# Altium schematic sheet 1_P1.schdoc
size 355 x 309 mm; Symbol: Sheet-Symbol_A3; Device: Sheet-Symbol_A3; @Page Name: P1; @Create Date: 2022-11-13; @Page Count: 1; @Page No: 1; @Project Name: RGB_语音小灯_RGB; @Schematic Name: Schematic1; @Update Date: 2023-01-12
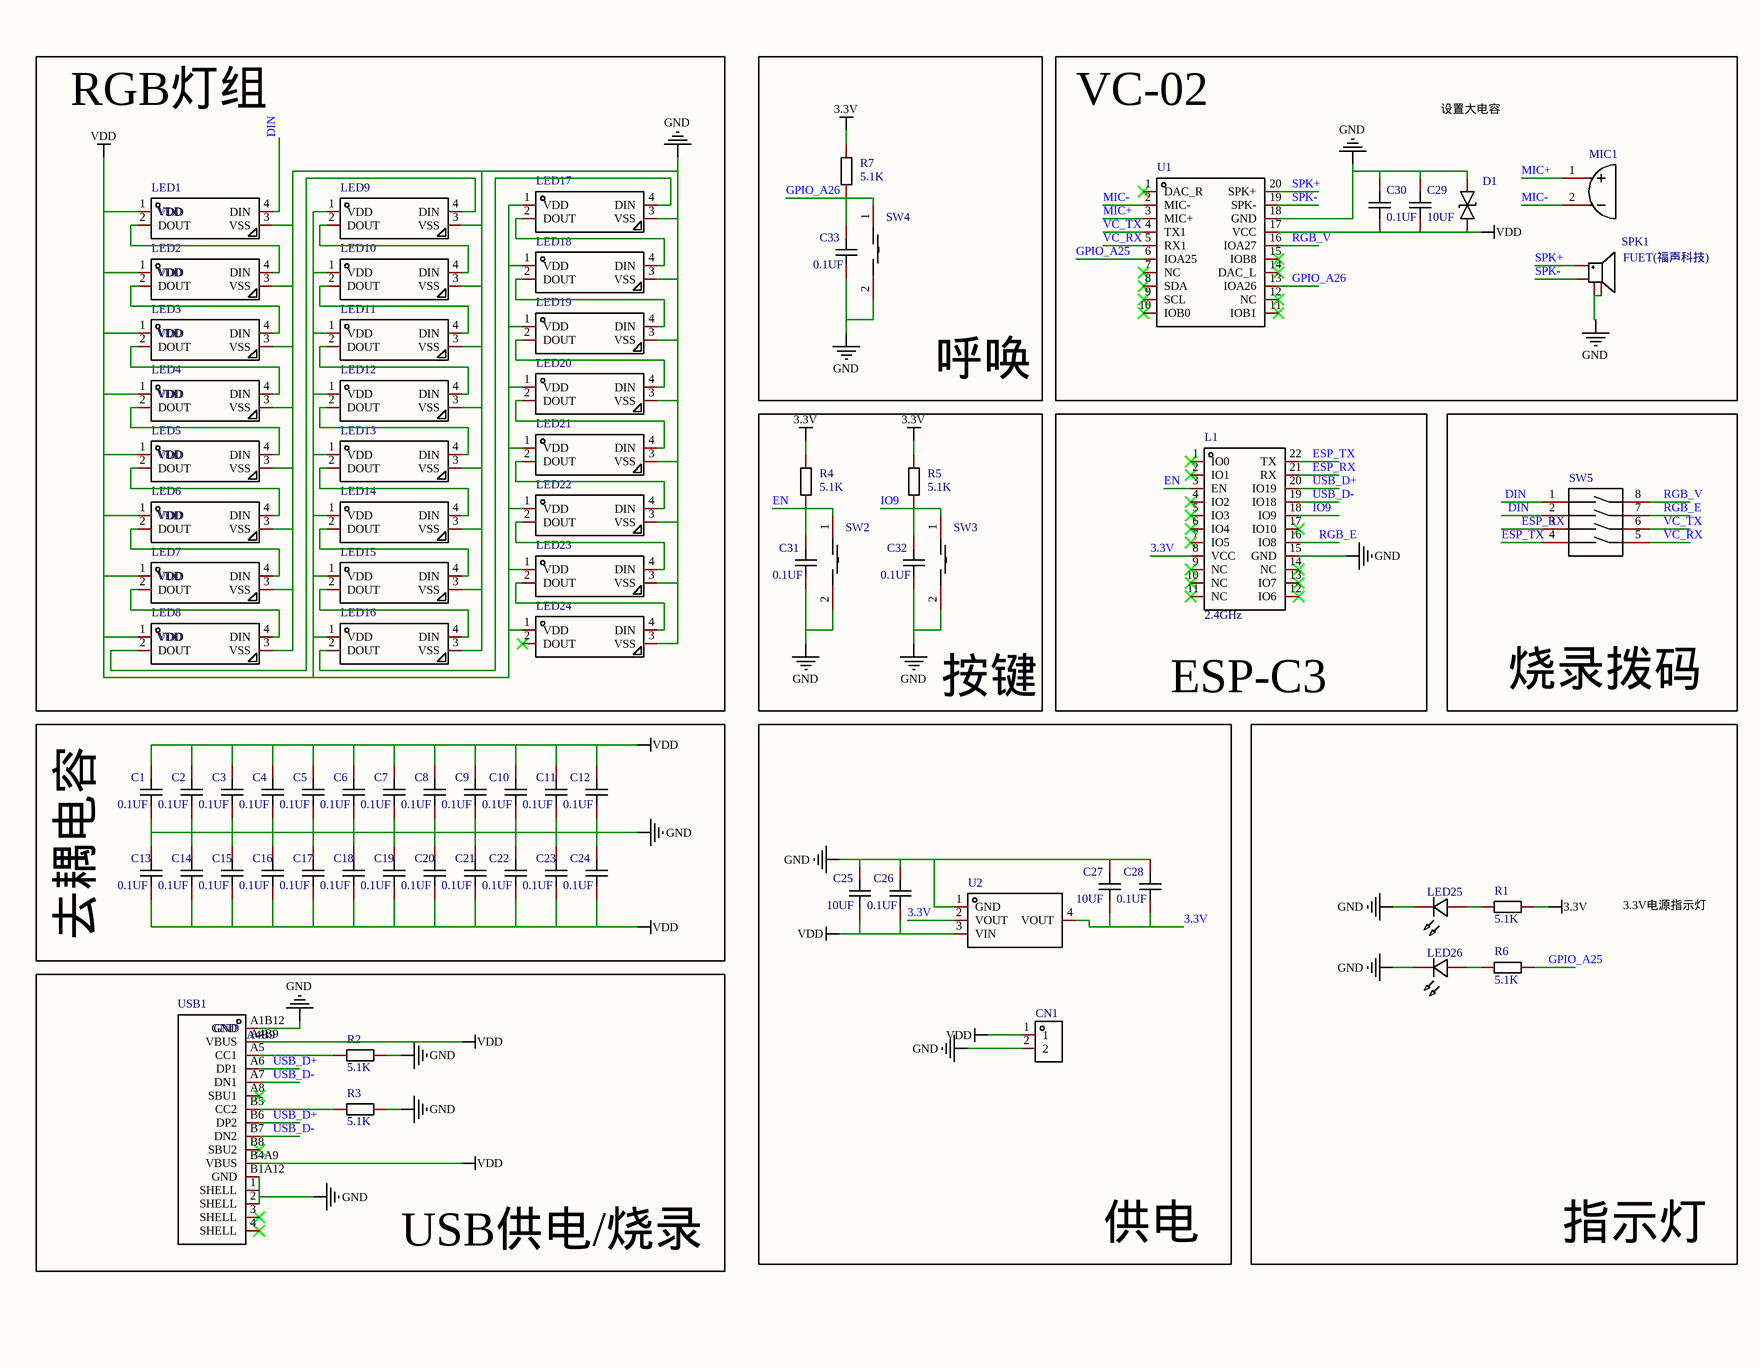
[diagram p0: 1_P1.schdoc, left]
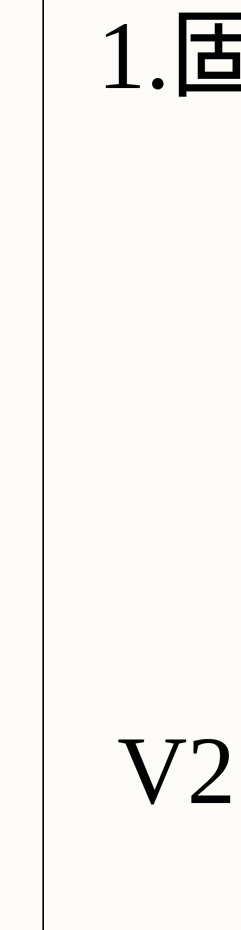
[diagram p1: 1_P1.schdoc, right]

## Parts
C1  value 0.1UF  [C0603]  (hidden comment: CAP_0603)
C2  value 0.1UF  [C0603]  (hidden comment: CAP_0603)
C3  value 0.1UF  [C0603]  (hidden comment: CAP_0603)
C4  value 0.1UF  [C0603]  (hidden comment: CAP_0603)
C5  value 0.1UF  [C0603]  (hidden comment: CAP_0603)
C6  value 0.1UF  [C0603]  (hidden comment: CAP_0603)
C7  value 0.1UF  [C0603]  (hidden comment: CAP_0603)
C8  value 0.1UF  [C0603]  (hidden comment: CAP_0603)
C9  value 0.1UF  [C0603]  (hidden comment: CAP_0603)
C10  value 0.1UF  [C0603]  (hidden comment: CAP_0603)
C11  value 0.1UF  [C0603]  (hidden comment: CAP_0603)
C12  value 0.1UF  [C0603]  (hidden comment: CAP_0603)
C13  value 0.1UF  [C0603]  (hidden comment: CAP_0603)
C14  value 0.1UF  [C0603]  (hidden comment: CAP_0603)
C15  value 0.1UF  [C0603]  (hidden comment: CAP_0603)
C16  value 0.1UF  [C0603]  (hidden comment: CAP_0603)
C17  value 0.1UF  [C0603]  (hidden comment: CAP_0603)
C18  value 0.1UF  [C0603]  (hidden comment: CAP_0603)
C19  value 0.1UF  [C0603]  (hidden comment: CAP_0603)
C20  value 0.1UF  [C0603]  (hidden comment: CAP_0603)
C21  value 0.1UF  [C0603]  (hidden comment: CAP_0603)
C22  value 0.1UF  [C0603]  (hidden comment: CAP_0603)
C23  value 0.1UF  [C0603]  (hidden comment: CAP_0603)
C24  value 0.1UF  [C0603]  (hidden comment: CAP_0603)
C25  value 10UF  [C0603]  (hidden comment: CAP_0603)
C26  value 0.1UF  [C0603]  (hidden comment: CAP_0603)
C27  value 10UF  [C0603]  (hidden comment: CAP_0603)
C28  value 0.1UF  [C0603]  (hidden comment: CAP_0603)
C29  value 10UF  [C0603]  (hidden comment: CAP_0603)
C30  value 0.1UF  [C0603]  (hidden comment: CAP_0603)
C31  value 0.1UF  [C0603]  (hidden comment: CAP_0603)
C32  value 0.1UF  [C0603]  (hidden comment: CAP_0603)
C33  value 0.1UF  [C0603]  (hidden comment: CAP_0603)
CN1  HDGC2501WR-2P  [CONN-TH_2P-P2.50_HDGC2501WR-2P]  (value not drawn)
D1  SESD3Z5C  [SOD-323_L1.7-W1.3-LS2.5-BI]  (value not drawn)
L1  value 2.4GHz  [WIRELM-SMD_ESP-C3-12F-2M]  (hidden comment: ESP-C3-12F-2M)
LED1  NAME: VDD  [LED-SMD_4P-L5.0-W5.0-TL_WS2812B-B]  (hidden comment: WS2812B-B)
LED2  NAME: VDD  [LED-SMD_4P-L5.0-W5.0-TL_WS2812B-B]  (hidden comment: WS2812B-B)
LED3  NAME: VDD  [LED-SMD_4P-L5.0-W5.0-TL_WS2812B-B]  (hidden comment: WS2812B-B)
LED4  NAME: VDD  [LED-SMD_4P-L5.0-W5.0-TL_WS2812B-B]  (hidden comment: WS2812B-B)
LED5  NAME: VDD  [LED-SMD_4P-L5.0-W5.0-TL_WS2812B-B]  (hidden comment: WS2812B-B)
LED6  NAME: VDD  [LED-SMD_4P-L5.0-W5.0-TL_WS2812B-B]  (hidden comment: WS2812B-B)
LED7  NAME: VDD  [LED-SMD_4P-L5.0-W5.0-TL_WS2812B-B]  (hidden comment: WS2812B-B)
LED8  NAME: VDD  [LED-SMD_4P-L5.0-W5.0-TL_WS2812B-B]  (hidden comment: WS2812B-B)
LED9  WS2812B-B  [LED-SMD_4P-L5.0-W5.0-TL_WS2812B-B]  (value not drawn)
LED10  WS2812B-B  [LED-SMD_4P-L5.0-W5.0-TL_WS2812B-B]  (value not drawn)
LED11  WS2812B-B  [LED-SMD_4P-L5.0-W5.0-TL_WS2812B-B]  (value not drawn)
LED12  WS2812B-B  [LED-SMD_4P-L5.0-W5.0-TL_WS2812B-B]  (value not drawn)
LED13  WS2812B-B  [LED-SMD_4P-L5.0-W5.0-TL_WS2812B-B]  (value not drawn)
LED14  WS2812B-B  [LED-SMD_4P-L5.0-W5.0-TL_WS2812B-B]  (value not drawn)
LED15  WS2812B-B  [LED-SMD_4P-L5.0-W5.0-TL_WS2812B-B]  (value not drawn)
LED16  WS2812B-B  [LED-SMD_4P-L5.0-W5.0-TL_WS2812B-B]  (value not drawn)
LED17  WS2812B-B  [LED-SMD_4P-L5.0-W5.0-TL_WS2812B-B]  (value not drawn)
LED18  WS2812B-B  [LED-SMD_4P-L5.0-W5.0-TL_WS2812B-B]  (value not drawn)
LED19  WS2812B-B  [LED-SMD_4P-L5.0-W5.0-TL_WS2812B-B]  (value not drawn)
LED20  WS2812B-B  [LED-SMD_4P-L5.0-W5.0-TL_WS2812B-B]  (value not drawn)
LED21  WS2812B-B  [LED-SMD_4P-L5.0-W5.0-TL_WS2812B-B]  (value not drawn)
LED22  WS2812B-B  [LED-SMD_4P-L5.0-W5.0-TL_WS2812B-B]  (value not drawn)
LED23  WS2812B-B  [LED-SMD_4P-L5.0-W5.0-TL_WS2812B-B]  (value not drawn)
LED24  WS2812B-B  [LED-SMD_4P-L5.0-W5.0-TL_WS2812B-B]  (value not drawn)
LED25  LED_0603-R  [LED0603-RD_BLUE]  (value not drawn)
LED26  LED_0603-R  [LED0603-RD_BLUE]  (value not drawn)
MIC1  GMI4015P-2C-42db  [MIC-TH_BD4.0-P1.40-D0.4-L-FD]  (value not drawn)
R1  value 5.1K  [R0603]  (hidden comment: Res_0603)
R2  value 5.1K  [R0603]  (hidden comment: Res_0603)
R3  value 5.1K  [R0603]  (hidden comment: Res_0603)
R4  value 5.1K  [R0603]  (hidden comment: Res_0603)
R5  value 5.1K  [R0603]  (hidden comment: Res_0603)
R6  value 5.1K  [R0603]  (hidden comment: Res_0603)
R7  value 5.1K  [R0603]  (hidden comment: Res_0603)
SPK1  Manufacturer: FUET(福声科技)  [BUZ-SMD_4P-L13.0-W13.0-P11.4-BL]  (hidden comment: FS-1340)
SW2  B3U-1000P  [KEY-SMD_B3U-1000PM]  (value not drawn)
SW3  B3U-1000P  [KEY-SMD_B3U-1000PM]  (value not drawn)
SW4  B3U-1000P  [KEY-SMD_B3U-1000PM]  (value not drawn)
SW5  DSHP04TS-S  [SW-SMD_8P-L6.7-W5.4-P1.27-LS8.5]  (value not drawn)
U1  VC-02_CN  [COMM-SMD_VC-02_CN]  (value not drawn)
U2  AMS1117-2.5_C498436  [SOT-223-3_L6.7-W3.7-P2.30-LS7.0-BR]  (value not drawn)
USB1  NAME: GND  NUMBER: A4B9  [USB-C-SMD_TYPE-C16PIN]  (hidden comment: TYPE-C16PIN)

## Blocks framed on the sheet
RGB灯组: LED1-LED24
呼唤: C33 R7 SW4
VC-02: C29 C30 D1 MIC1 SPK1 U1
按键: C31 C32 R4 R5 SW2 SW3
ESP-C3: L1
烧录拨码: SW5
去耦电容: C1-C24
供电: C25-C28 CN1 U2
指示灯: LED25 LED26 R1 R6
USB供电/烧录: R2 R3 USB1

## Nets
3.3V: C27.1 C28.1 L1.8(VCC) R1.2 R4.2 R5.2 R7.2 U2.2(VOUT) U2.4(VOUT)
GND: C1.1 C2.1 C3.1 C4.1 C5.1 C6.1 C7.1 C8.1 C9.1 C10.1 C11.1 C12.1 C13.2 C14.2 C15.2 C16.2 C17.2 C18.2 C19.2 C20.2 C21.2 C22.2 C23.2 C24.2 C25.2 C26.2 C27.2 C28.2 C29.1 C30.1 C31.2 C32.2 C33.2 CN1.2 D1.2 L1.15(GND) LED1.3(VSS) LED2.3(VSS) LED3.3(VSS) LED4.3(VSS) LED5.3(VSS) LED6.3(VSS) LED7.3(VSS) LED8.3(VSS) LED9.3(VSS) LED10.3(VSS) LED11.3(VSS) LED12.3(VSS) LED13.3(VSS) LED14.3(VSS) LED15.3(VSS) LED16.3(VSS) LED17.3(VSS) LED18.3(VSS) LED19.3(VSS) LED20.3(VSS) LED21.3(VSS) LED22.3(VSS) LED23.3(VSS) LED24.3(VSS) LED25.1(C) LED26.1(C) R2.2 R3.2 SPK1.3 SPK1.4 SW2.2 SW3.2 SW4.2 U1.18(GND) U2.1(GND) USB1.1(SHELL) USB1.2(SHELL) USB1.A1B12(GND) USB1.B1A12(GND)
VDD: C1.2 C2.2 C3.2 C4.2 C5.2 C6.2 C7.2 C8.2 C9.2 C10.2 C11.2 C12.2 C13.1 C14.1 C15.1 C16.1 C17.1 C18.1 C19.1 C20.1 C21.1 C22.1 C23.1 C24.1 C25.1 C26.1 C29.2 C30.2 CN1.1 D1.1 LED1.1(VDD) LED2.1(VDD) LED3.1(VDD) LED4.1(VDD) LED5.1(VDD) LED6.1(VDD) LED7.1(VDD) LED8.1(VDD) LED9.1(VDD) LED10.1(VDD) LED11.1(VDD) LED12.1(VDD) LED13.1(VDD) LED14.1(VDD) LED15.1(VDD) LED16.1(VDD) LED17.1(VDD) LED18.1(VDD) LED19.1(VDD) LED20.1(VDD) LED21.1(VDD) LED22.1(VDD) LED23.1(VDD) LED24.1(VDD) U1.17(VCC) U2.3(VIN) USB1.A4B9(VBUS) USB1.B4A9(VBUS)
DIN: LED1.4(DIN) SW5.1 SW5.2
EN: C31.1 L1.3(EN) R4.1 SW2.1
ESP_RX: L1.21(RX) SW5.3
ESP_TX: L1.22(TX) SW5.4
GPIO_A25: R6.2 U1.6(IOA25)
GPIO_A26: C33.1 R7.1 SW4.1 U1.13(IOA26)
IO9: C32.1 L1.18(IO9) R5.1 SW3.1
MIC+: MIC1.1 U1.3(MIC+)
MIC-: MIC1.2 U1.2(MIC-)
RGB_E: L1.16(IO8) SW5.7
RGB_V: SW5.8 U1.16(IOA27)
SPK+: SPK1.1(+) U1.20(SPK+)
SPK-: SPK1.2(-) U1.19(SPK-)
USB_D+: L1.20(IO19) USB1.A6(DP1) USB1.B6(DP2)
USB_D-: L1.19(IO18) USB1.A7(DN1) USB1.B7(DN2)
VC_RX: SW5.5 U1.5(RX1)
VC_TX: SW5.6 U1.4(TX1)
NetLED1_2: LED1.2(DOUT) LED2.4(DIN)
NetLED2_2: LED2.2(DOUT) LED3.4(DIN)
NetLED3_2: LED3.2(DOUT) LED4.4(DIN)
NetLED4_2: LED4.2(DOUT) LED5.4(DIN)
NetLED5_2: LED5.2(DOUT) LED6.4(DIN)
NetLED6_2: LED6.2(DOUT) LED7.4(DIN)
NetLED7_2: LED7.2(DOUT) LED8.4(DIN)
NetLED8_2: LED8.2(DOUT) LED9.4(DIN)
NetLED9_2: LED9.2(DOUT) LED10.4(DIN)
NetLED10_2: LED10.2(DOUT) LED11.4(DIN)
NetLED11_2: LED11.2(DOUT) LED12.4(DIN)
NetLED12_2: LED12.2(DOUT) LED13.4(DIN)
NetLED13_2: LED13.2(DOUT) LED14.4(DIN)
NetLED14_2: LED14.2(DOUT) LED15.4(DIN)
NetLED15_2: LED15.2(DOUT) LED16.4(DIN)
NetLED16_2: LED16.2(DOUT) LED17.4(DIN)
NetLED17_2: LED17.2(DOUT) LED18.4(DIN)
NetLED18_2: LED18.2(DOUT) LED19.4(DIN)
NetLED19_2: LED19.2(DOUT) LED20.4(DIN)
NetLED20_2: LED20.2(DOUT) LED21.4(DIN)
NetLED21_2: LED21.2(DOUT) LED22.4(DIN)
NetLED22_2: LED22.2(DOUT) LED23.4(DIN)
NetLED23_2: LED23.2(DOUT) LED24.4(DIN)
NetLED25_2: LED25.2(A) R1.1
NetLED26_2: LED26.2(A) R6.1
NetR2_1: R2.1 USB1.A5(CC1)
NetR3_1: R3.1 USB1.B5(CC2)

Not connected (* = marked no-connect by the designer): L1 1(IO0)* 2(IO1)* 4(IO2)* 5(IO3)* 6(IO4)* 7(IO5)* 9(NC)* 10(NC)* 11(NC)* 12(IO6)* 13(IO7)* 14(NC)* 17(IO10)*; LED24 2(DOUT)*; U1 1(DAC_R)* 7(NC)* 8(SDA)* 9(SCL)* 10(IOB0)* 11(IOB1)* 12(NC)* 14(DAC_L)* 15(IOB8)*; USB1 3(SHELL)* 4(SHELL)* A8(SBU1)* B8(SBU2)*

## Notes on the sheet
- 设置大电容
- 1.固定孔
- 3.3V电源指示灯
- V2.0

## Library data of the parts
C1-C33 = CAP_0603: Symbol: C1210X7R475K630NT; Convert to PCB: yes
CN1 = HDGC2501WR-2P: Manufacturer: HDGC(华德共创); Add into BOM: yes
D1 = SESD3Z5C: 极性:Bidirectional;反向关断电压（典型值）:5V;击穿电压（最小值）:5.8V;箝位电压:-;峰值脉冲电流（10/1000us）:-;; Manufacturer: SINO-IC(光宇睿芯); Add into BOM: yes; Voltage - Reverse Standoff (Typ): 5V; Voltage - Breakdown (Min): 5.8V
L1 = ESP-C3-12F-2M: 频率:2.4GHz;发射功率:-;核心处理器:RISC-V;天线形式:板载 PCB 天线/IPEX 座子兼容;接收灵敏度:-96dBm;; Manufacturer: Ai-Thinker(安信可); Add into BOM: yes; Core Processor: RISC-V; Support Interface: I2C；GPIO；UART；PWM；ADC；I2S; Wireless Standard: 802.11b/g/n; Operating Voltage: 3.3V; Receive  Current: 84mA; Send  Current: 345mA; Sensitivity: -96dBm
LED1-LED24 = WS2812B-B: 发光颜色:RGB三色;; Manufacturer: worldsemi; Add into BOM: yes; Emitted Color: RGB三色
LED25 LED26 = LED_0603-R: 发光颜色:红灯;二极管配置:-;透镜颜色:无色透明;主波长:617.5nm;峰值波长:632nm;色温:-;光通量(25时):-;测试电流:5mA;正向电压(VF):2.2V;发光强度:28.5mcd;功率:60mW;发光角度:120°;安装方式:-;工作温度:-40~+85;; Symbol: LED_R; Convert to PCB: yes
MIC1 = GMI4015P-2C-42db: Manufacturer: INGHAi(赢海); Add into BOM: yes
R1-R7 = Res_0603: Symbol: 电阻; Convert to PCB: yes
SPK1 = FS-1340: Add into BOM: yes
SW2-SW4 = B3U-1000P: 触点电流:50mA;额定电压(DC):12V;电路结构:单刀单掷;安装方式:立贴;按钮形状:圆形按钮;带灯:-;开关长度:3mm;开关宽度:2.5mm;开关高度:1.6mm;; Manufacturer: OMRON(欧姆龙); Add into BOM: yes; Contact Current: 50mA; Voltage Rating (DC): 12V; Circuit: 单刀单掷; Actuator Style: 圆形按钮; Switch Length: 3mm; Switch Width: 2.5mm; Switch Height: 1.6mm
SW5 = DSHP04TS-S: 类型:平拨，凹槽式;额定电流:25mA;额定电压:24V;电路结构:单刀单掷;开关位数:4;引脚样式:鸥翼型;引脚间距:1.27mm;工作温度:-20℃~+70℃;使用寿命:3000;颜色:黑色;; Manufacturer: XKB Connectivity(中国星坤); Add into BOM: yes; Current Rating: 25mA; Voltage Rating: 24V; Circuit: 单刀单掷; Number of Positions: 4; Pin Style: 鸥翼型; Operating Life: 3000
U1 = VC-02_CN: Manufacturer: Ai-Thinker(安信可); Add into BOM: yes
U2 = AMS1117-2.5_C498436: 输出类型:-;; Manufacturer: Slkor(萨科微); Add into BOM: yes
USB1 = TYPE-C16PIN: 连接器类型:Type-C;标准:-;公母:母座;触点数量:16;端口数量:1;安装方式:卧贴;额定电流 - 电源:3A;工作温度范围:-40~+85;; Manufacturer: SHOU HAN(首韩); Add into BOM: yes; Connector Type: Type-C; Gender: 母座; Number of Contacts: 16; Number of Ports: 1; Current Rating - Power (Max): 3A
